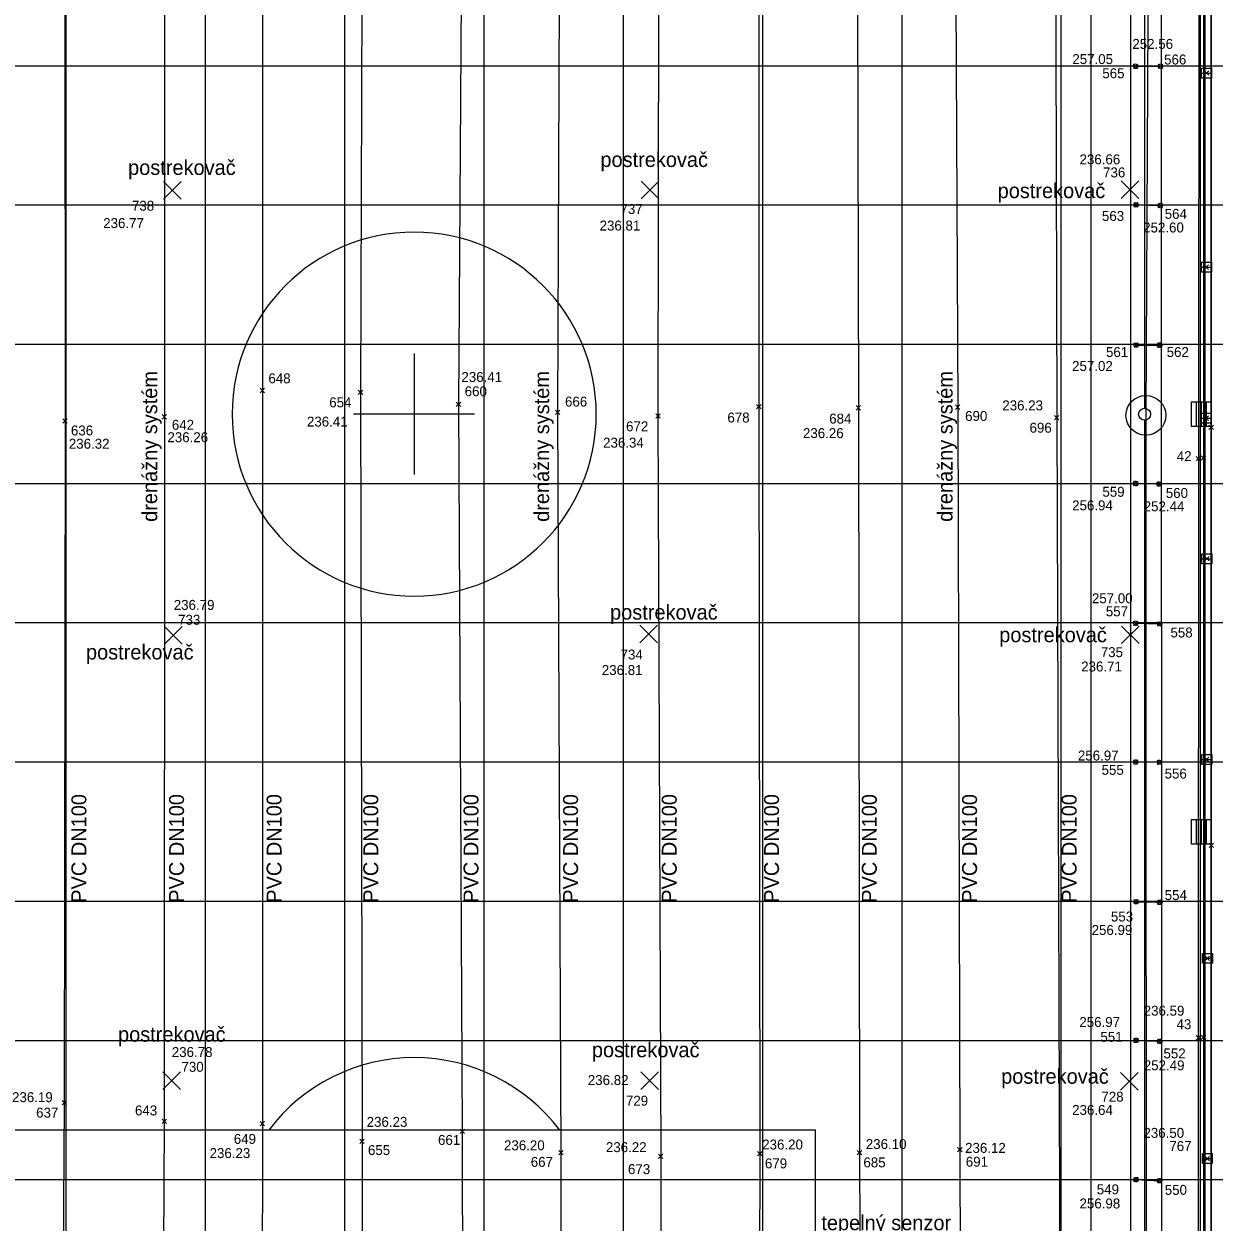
# Model space of a CAD drawing. Extents: x -264205 to -263659, y -1242401 to -1242060.
# Drawn here: x -263871.6 to -263811.8, y -1242205 to -1242144.8 of the extents above; entities that cross this region are included whole.
import ezdxf

# ---------------------------------------------------------------- set-up
doc = ezdxf.new("R2010")
doc.units = 0
for name, color, linetype in [('BOD_CISLO', 7, 'Continuous'), ('BOD_SYMBOL', 7, 'Continuous'), ('BOD_VYSKA', 7, 'Continuous'), ('KFA_SO_10-1_DRENAZNY_SYSTEM_IHRISKA', 7, 'Continuous'), ('KFA_SO_10-1_LIZATKA_POMOCNE', 7, 'Continuous'), ('KFA_SO_10-1_OBRUBNIKY_IHRISKO', 7, 'Continuous'), ('KFA_SO_10-1_POSTREKOVACE', 7, 'Continuous'), ('KFA_SO_10-1_STRECHY', 7, 'Continuous'), ('KFA_SO_10-1_TRIBUNA_C_OBVOD', 7, 'Continuous'), ('KFA_SO_10-1_VPUST_STADION_POKLOP', 7, 'Continuous'), ('KFA_SO_40-2-II_DAZDOVA_KANALIZACIA', 7, 'Continuous'), ('OSI_STAVBY_KFA', 7, 'Continuous'), ('POPIS', 7, 'Continuous'), ('SITUACIA_DSP_2D', 7, 'Continuous')]:
    doc.layers.add(name, color=color, linetype=linetype)

msp = doc.modelspace()

# ---------------------------------------------------------------- linework, layer by layer
at = {"layer": 'BOD_SYMBOL'}
for p, q in [((-263815.819, -1242147.002), (-263815.598, -1242146.781)), ((-263815.598, -1242147.002), (-263815.819, -1242146.781)), ((-263814.573, -1242147.002), (-263814.352, -1242146.782)), ((-263814.352, -1242147.002), (-263814.573, -1242146.782)), ((-263812.263, -1242147.35), (-263812.041, -1242147.13)), ((-263812.041, -1242147.35), (-263812.263, -1242147.13)), ((-263864.232, -1242153.24), (-263864.011, -1242153.019)), ((-263864.011, -1242153.24), (-263864.232, -1242153.019)), ((-263840.223, -1242153.231), (-263840.002, -1242153.009)), ((-263840.002, -1242153.231), (-263840.223, -1242153.009)), ((-263816.111, -1242153.208), (-263815.889, -1242152.987)), ((-263815.889, -1242153.208), (-263816.111, -1242152.987)), ((-263815.802, -1242153.971), (-263815.581, -1242153.749)), ((-263815.581, -1242153.971), (-263815.802, -1242153.749)), ((-263814.588, -1242154.007), (-263814.367, -1242153.785)), ((-263814.367, -1242154.007), (-263814.588, -1242153.785)), ((-263812.268, -1242157.105), (-263812.046, -1242156.883)), ((-263812.046, -1242157.105), (-263812.268, -1242156.883)), ((-263815.8, -1242161.024), (-263815.579, -1242160.802)), ((-263815.579, -1242161.024), (-263815.8, -1242160.802)), ((-263814.617, -1242161.025), (-263814.396, -1242160.805)), ((-263814.396, -1242161.025), (-263814.617, -1242160.805)), ((-263859.705, -1242163.305), (-263859.484, -1242163.083)), ((-263859.484, -1242163.305), (-263859.705, -1242163.083)), ((-263854.777, -1242163.391), (-263854.556, -1242163.171)), ((-263854.556, -1242163.391), (-263854.777, -1242163.171)), ((-263849.851, -1242163.995), (-263849.63, -1242163.774)), ((-263849.63, -1242163.995), (-263849.851, -1242163.774)), ((-263844.872, -1242164.406), (-263844.65, -1242164.184)), ((-263844.65, -1242164.406), (-263844.872, -1242164.184)), ((-263834.758, -1242164.12), (-263834.537, -1242163.9)), ((-263834.537, -1242164.12), (-263834.758, -1242163.9)), ((-263829.758, -1242164.176), (-263829.536, -1242163.954)), ((-263829.536, -1242164.176), (-263829.758, -1242163.954)), ((-263824.766, -1242164.144), (-263824.545, -1242163.923)), ((-263824.545, -1242164.144), (-263824.766, -1242163.923)), ((-263869.623, -1242164.833), (-263869.402, -1242164.613)), ((-263869.402, -1242164.833), (-263869.623, -1242164.613)), ((-263864.633, -1242164.63), (-263864.411, -1242164.409)), ((-263864.411, -1242164.63), (-263864.633, -1242164.409)), ((-263839.828, -1242164.58), (-263839.606, -1242164.36)), ((-263839.606, -1242164.58), (-263839.828, -1242164.36)), ((-263819.788, -1242164.676), (-263819.567, -1242164.454)), ((-263819.567, -1242164.676), (-263819.788, -1242164.454)), ((-263812.279, -1242164.695), (-263812.057, -1242164.475)), ((-263812.057, -1242164.695), (-263812.279, -1242164.475)), ((-263812.028, -1242165.156), (-263811.807, -1242164.934)), ((-263811.807, -1242165.156), (-263812.028, -1242164.934)), ((-263812.671, -1242166.732), (-263812.45, -1242166.512)), ((-263812.45, -1242166.732), (-263812.671, -1242166.512)), ((-263812.414, -1242166.701), (-263812.193, -1242166.481)), ((-263812.193, -1242166.701), (-263812.414, -1242166.481)), ((-263815.823, -1242167.981), (-263815.602, -1242167.759)), ((-263815.602, -1242167.981), (-263815.823, -1242167.759)), ((-263814.652, -1242168.004), (-263814.431, -1242167.782)), ((-263814.431, -1242168.004), (-263814.652, -1242167.782)), ((-263812.246, -1242171.764), (-263812.024, -1242171.542)), ((-263812.024, -1242171.764), (-263812.246, -1242171.542)), ((-263815.816, -1242175.007), (-263815.595, -1242174.785)), ((-263815.595, -1242175.007), (-263815.816, -1242174.785)), ((-263814.616, -1242175.042), (-263814.394, -1242174.822)), ((-263814.394, -1242175.042), (-263814.616, -1242174.822)), ((-263864.179, -1242175.617), (-263863.958, -1242175.396)), ((-263863.958, -1242175.617), (-263864.179, -1242175.396)), ((-263840.291, -1242175.542), (-263840.07, -1242175.32)), ((-263840.07, -1242175.542), (-263840.291, -1242175.32)), ((-263816.084, -1242175.586), (-263815.863, -1242175.366)), ((-263815.863, -1242175.586), (-263816.084, -1242175.366)), ((-263815.817, -1242181.98), (-263815.595, -1242181.758)), ((-263815.595, -1242181.98), (-263815.817, -1242181.758)), ((-263814.629, -1242181.995), (-263814.408, -1242181.775)), ((-263814.408, -1242181.995), (-263814.629, -1242181.775)), ((-263812.247, -1242181.855), (-263812.026, -1242181.633)), ((-263812.026, -1242181.855), (-263812.247, -1242181.633)), ((-263812.025, -1242186.164), (-263811.804, -1242185.943)), ((-263811.804, -1242186.164), (-263812.025, -1242185.943)), ((-263815.799, -1242189.008), (-263815.578, -1242188.788)), ((-263815.578, -1242189.008), (-263815.799, -1242188.788)), ((-263814.607, -1242189.032), (-263814.386, -1242188.812)), ((-263814.386, -1242189.032), (-263814.607, -1242188.812)), ((-263812.217, -1242191.85), (-263811.996, -1242191.629)), ((-263811.996, -1242191.85), (-263812.217, -1242191.629)), ((-263812.672, -1242195.849), (-263812.451, -1242195.627)), ((-263812.451, -1242195.849), (-263812.672, -1242195.627)), ((-263812.411, -1242195.823), (-263812.19, -1242195.603)), ((-263812.19, -1242195.823), (-263812.411, -1242195.603)), ((-263815.802, -1242195.974), (-263815.58, -1242195.752)), ((-263815.58, -1242195.974), (-263815.802, -1242195.752)), ((-263814.612, -1242196.022), (-263814.391, -1242195.802)), ((-263814.391, -1242196.022), (-263814.612, -1242195.802)), ((-263864.266, -1242198.005), (-263864.045, -1242197.784)), ((-263864.045, -1242198.005), (-263864.266, -1242197.784)), ((-263840.246, -1242197.997), (-263840.024, -1242197.775)), ((-263840.024, -1242197.997), (-263840.246, -1242197.775)), ((-263816.144, -1242198.029), (-263815.924, -1242197.808)), ((-263815.924, -1242198.029), (-263816.144, -1242197.808)), ((-263869.663, -1242199.113), (-263869.442, -1242198.893)), ((-263869.442, -1242199.113), (-263869.663, -1242198.893)), ((-263864.638, -1242200.049), (-263864.416, -1242199.828)), ((-263864.416, -1242200.049), (-263864.638, -1242199.828)), ((-263859.704, -1242200.166), (-263859.483, -1242199.944)), ((-263859.483, -1242200.166), (-263859.704, -1242199.944)), ((-263849.664, -1242200.552), (-263849.443, -1242200.33)), ((-263849.443, -1242200.552), (-263849.664, -1242200.33)), ((-263854.698, -1242201.046), (-263854.476, -1242200.826)), ((-263854.476, -1242201.046), (-263854.698, -1242200.826)), ((-263844.707, -1242201.623), (-263844.486, -1242201.403)), ((-263844.486, -1242201.623), (-263844.707, -1242201.403)), ((-263839.691, -1242201.799), (-263839.47, -1242201.579)), ((-263839.47, -1242201.799), (-263839.691, -1242201.579)), ((-263834.707, -1242201.667), (-263834.486, -1242201.445)), ((-263834.486, -1242201.667), (-263834.707, -1242201.445)), ((-263829.699, -1242201.623), (-263829.478, -1242201.403)), ((-263829.478, -1242201.623), (-263829.699, -1242201.403)), ((-263824.66, -1242201.465), (-263824.438, -1242201.245)), ((-263824.438, -1242201.465), (-263824.66, -1242201.245)), ((-263812.22, -1242201.921), (-263811.998, -1242201.7)), ((-263811.998, -1242201.921), (-263812.22, -1242201.7)), ((-263815.802, -1242202.975), (-263815.581, -1242202.755)), ((-263815.581, -1242202.975), (-263815.802, -1242202.755)), ((-263814.622, -1242203.032), (-263814.4, -1242202.811)), ((-263814.4, -1242203.032), (-263814.622, -1242202.811))]:
    msp.add_line(p, q, dxfattribs=at)
at = {"layer": 'KFA_SO_10-1_DRENAZNY_SYSTEM_IHRISKA'}
for p, q in [((-263869.556, -1242111.232), (-263869.513, -1242164.723)), ((-263864.517, -1242111.831), (-263864.522, -1242164.519)), ((-263859.568, -1242112.454), (-263859.595, -1242163.194)), ((-263854.492, -1242112.7), (-263854.666, -1242163.281)), ((-263849.405, -1242112.937), (-263849.741, -1242163.884)), ((-263844.574, -1242112.927), (-263844.761, -1242164.295)), ((-263839.653, -1242112.911), (-263839.717, -1242164.47)), ((-263834.662, -1242113.858), (-263834.648, -1242164.01)), ((-263829.735, -1242114.023), (-263829.647, -1242164.065)), ((-263824.874, -1242113.88), (-263824.655, -1242164.033))]:
    msp.add_line(p, q, dxfattribs=at)
for points in [[(-263819.808, -1242114.324), (-263819.677, -1242164.565), (-263819.485, -1242218.367)], [(-263859.595, -1242163.194), (-263859.594, -1242200.055), (-263859.624, -1242218.088)], [(-263854.666, -1242163.281), (-263854.587, -1242200.936), (-263854.584, -1242216.781)], [(-263849.741, -1242163.884), (-263849.553, -1242200.441), (-263849.516, -1242217.262)], [(-263844.761, -1242164.295), (-263844.596, -1242201.513), (-263844.587, -1242217.331)], [(-263834.648, -1242164.01), (-263834.596, -1242201.556), (-263834.64, -1242218.417)], [(-263829.647, -1242164.065), (-263829.589, -1242201.513), (-263829.518, -1242218.027)], [(-263824.655, -1242164.033), (-263824.549, -1242201.355), (-263824.496, -1242218.682)], [(-263869.513, -1242164.723), (-263869.552, -1242199.003), (-263869.699, -1242219.776)], [(-263864.522, -1242164.519), (-263864.527, -1242199.938), (-263864.632, -1242219.068)], [(-263839.717, -1242164.47), (-263839.58, -1242201.689), (-263839.608, -1242217.689)]]:
    msp.add_lwpolyline(points, dxfattribs=at)
at = {"layer": 'KFA_SO_10-1_LIZATKA_POMOCNE'}
for p, q in [((-263815.709, -1242146.891), (-263814.463, -1242146.892)), ((-263815.692, -1242153.86), (-263814.477, -1242153.896)), ((-263815.689, -1242160.913), (-263814.507, -1242160.915)), ((-263815.713, -1242167.87), (-263814.541, -1242167.893)), ((-263815.705, -1242174.896), (-263814.505, -1242174.932)), ((-263815.706, -1242181.869), (-263814.519, -1242181.885)), ((-263815.688, -1242188.898), (-263814.497, -1242188.922)), ((-263815.691, -1242195.863), (-263814.502, -1242195.912)), ((-263815.692, -1242202.865), (-263814.511, -1242202.921))]:
    msp.add_line(p, q, dxfattribs=at)
for centre, major_axis, ratio in [((-263815.709, -1242146.891), (0.022, -0.111), 0.955047), ((-263814.463, -1242146.892), (-0.008, -0.115), 0.990623), ((-263815.692, -1242153.86), (0.0495, 0.0979), 0.976376), ((-263814.477, -1242153.896), (0.104, -0.043), 0.992511), ((-263815.689, -1242160.913), (0.031, -0.105), 0.950619), ((-263814.507, -1242160.915), (0.0934, -0.0705), 0.992164), ((-263815.713, -1242167.87), (0.053, 0.107), 0.970811), ((-263814.541, -1242167.893), (0.107, 0.029), 0.998784), ((-263815.705, -1242174.896), (0.028, 0.113), 0.977707), ((-263814.505, -1242174.932), (0.0777, -0.0759), 0.907938), ((-263815.706, -1242181.869), (0.0648, 0.0887), 0.97856), ((-263814.519, -1242181.885), (0.103, -0.016), 0.997627), ((-263815.688, -1242188.898), (-0.014, -0.11), 0.978866), ((-263814.497, -1242188.922), (0.0814, -0.0864), 0.990444), ((-263815.691, -1242195.863), (0.0926, 0.0706), 0.985437), ((-263814.502, -1242195.912), (0.109, 0.032), 0.999252), ((-263815.692, -1242202.865), (-0.013, -0.114), 0.974636), ((-263814.511, -1242202.921), (-0.037, -0.106), 0.999546)]:
    msp.add_ellipse(centre, major_axis=major_axis, ratio=ratio, dxfattribs=at)
at = {"layer": 'KFA_SO_10-1_OBRUBNIKY_IHRISKO'}
for points in [[(-263812.554, -1242108.944), (-263812.55, -1242123.834), (-263812.543, -1242140.463), (-263812.561, -1242166.622), (-263812.562, -1242195.738), (-263812.559, -1242219.298)], [(-263812.302, -1242108.944), (-263812.301, -1242123.86), (-263812.298, -1242140.481), (-263812.303, -1242166.591), (-263812.301, -1242195.713), (-263812.296, -1242220.436)]]:
    msp.add_lwpolyline(points, dxfattribs=at)
at = {"layer": 'KFA_SO_10-1_POSTREKOVACE'}
for p, q in [((-263864.564, -1242153.571), (-263863.68, -1242152.687)), ((-263863.68, -1242153.571), (-263864.564, -1242152.687)), ((-263840.554, -1242153.562), (-263839.67, -1242152.678)), ((-263839.67, -1242153.562), (-263840.554, -1242152.678)), ((-263816.442, -1242153.539), (-263815.558, -1242152.655)), ((-263815.558, -1242153.539), (-263816.442, -1242152.655)), ((-263864.51, -1242175.948), (-263863.626, -1242175.064)), ((-263863.626, -1242175.948), (-263864.51, -1242175.064)), ((-263840.623, -1242175.873), (-263839.739, -1242174.989)), ((-263839.739, -1242175.873), (-263840.623, -1242174.989)), ((-263816.416, -1242175.918), (-263815.532, -1242175.034)), ((-263815.532, -1242175.918), (-263816.416, -1242175.034)), ((-263864.597, -1242198.336), (-263863.713, -1242197.452)), ((-263863.713, -1242198.336), (-263864.597, -1242197.452)), ((-263840.577, -1242198.328), (-263839.693, -1242197.444)), ((-263839.693, -1242198.328), (-263840.577, -1242197.444)), ((-263816.476, -1242198.36), (-263815.592, -1242197.476)), ((-263815.592, -1242198.36), (-263816.476, -1242197.476))]:
    msp.add_line(p, q, dxfattribs=at)
at = {"layer": 'KFA_SO_10-1_STRECHY'}
msp.add_line((-263814.432, -1242109.405), (-263814.411, -1242219.389), dxfattribs=at)
at = {"layer": 'KFA_SO_10-1_TRIBUNA_C_OBVOD'}
msp.add_lwpolyline([(-263811.9, -1242108.121), (-263811.778, -1242108.42), (-263811.904, -1242108.455), (-263811.9, -1242110.523), (-263811.9, -1242110.524), (-263811.903, -1242123.046), (-263811.913, -1242144.045), (-263811.917, -1242165.045), (-263811.915, -1242186.053), (-263811.913, -1242207.043), (-263811.91, -1242218.257), (-263811.909, -1242218.258), (-263811.907, -1242220.315), (-263811.793, -1242220.368), (-263811.913, -1242220.663)], dxfattribs=at)
at = {"layer": 'KFA_SO_10-1_VPUST_STADION_POKLOP'}
for p, q in [((-263812.152, -1242147.24), (-263812.152, -1242147.24)), ((-263812.157, -1242156.994), (-263812.157, -1242156.994)), ((-263812.168, -1242164.585), (-263812.168, -1242164.585)), ((-263812.135, -1242171.653), (-263812.135, -1242171.653)), ((-263812.137, -1242181.744), (-263812.137, -1242181.744)), ((-263812.106, -1242191.739), (-263812.106, -1242191.739)), ((-263812.109, -1242201.81), (-263812.109, -1242201.81))]:
    msp.add_line(p, q, dxfattribs=at)
for points in [[(-263812.402, -1242147.24), (-263812.402, -1242146.99), (-263811.902, -1242146.99), (-263811.902, -1242147.49), (-263812.402, -1242147.49), (-263812.402, -1242147.24), (-263811.902, -1242147.24)], [(-263812.407, -1242156.994), (-263812.407, -1242156.744), (-263811.907, -1242156.744), (-263811.907, -1242157.244), (-263812.407, -1242157.244), (-263812.407, -1242156.994), (-263811.907, -1242156.994)], [(-263812.418, -1242164.585), (-263812.418, -1242164.335), (-263811.918, -1242164.335), (-263811.918, -1242164.835), (-263812.418, -1242164.835), (-263812.418, -1242164.585), (-263811.918, -1242164.585)], [(-263812.385, -1242171.653), (-263812.385, -1242171.403), (-263811.885, -1242171.403), (-263811.885, -1242171.903), (-263812.385, -1242171.903), (-263812.385, -1242171.653), (-263811.885, -1242171.653)], [(-263812.387, -1242181.744), (-263812.387, -1242181.494), (-263811.887, -1242181.494), (-263811.887, -1242181.994), (-263812.387, -1242181.994), (-263812.387, -1242181.744), (-263811.887, -1242181.744)], [(-263812.356, -1242191.739), (-263812.356, -1242191.489), (-263811.856, -1242191.489), (-263811.856, -1242191.989), (-263812.356, -1242191.989), (-263812.356, -1242191.739), (-263811.856, -1242191.739)], [(-263812.359, -1242201.81), (-263812.359, -1242201.56), (-263811.859, -1242201.56), (-263811.859, -1242202.06), (-263812.359, -1242202.06), (-263812.359, -1242201.81), (-263811.859, -1242201.81)]]:
    msp.add_lwpolyline(points, dxfattribs=at)
at = {"layer": 'KFA_SO_40-2-II_DAZDOVA_KANALIZACIA'}
msp.add_lwpolyline([(-263814.907, -1242107.856), (-263815.198, -1242164.443), (-263815.189, -1242220.791), (-263852.152, -1242220.736), (-263888.701, -1242220.786), (-263906.731, -1242239.259)], dxfattribs=at)
msp.add_circle((-263815.198, -1242164.443), 1, dxfattribs=at)
at = {"layer": 'OSI_STAVBY_KFA'}
for p, q in [((-263869.468, -1242083.237), (-263869.468, -1242246.707)), ((-263862.468, -1242083.237), (-263862.468, -1242246.707)), ((-263855.468, -1242083.237), (-263855.468, -1242246.707)), ((-263848.468, -1242083.237), (-263848.468, -1242246.707)), ((-263841.468, -1242083.237), (-263841.468, -1242246.707)), ((-263834.468, -1242083.237), (-263834.468, -1242246.707)), ((-263827.468, -1242083.237), (-263827.468, -1242246.707)), ((-263819.468, -1242083.237), (-263819.468, -1242246.707)), ((-263812.468, -1242083.237), (-263812.468, -1242246.707)), ((-263792.653, -1242146.882), (-263909.343, -1242146.882)), ((-263792.653, -1242153.882), (-263909.343, -1242153.882)), ((-263792.653, -1242160.882), (-263909.343, -1242160.882)), ((-263792.653, -1242167.882), (-263909.343, -1242167.882)), ((-263792.653, -1242174.882), (-263909.343, -1242174.882)), ((-263792.653, -1242181.882), (-263909.343, -1242181.882)), ((-263792.653, -1242188.882), (-263909.343, -1242188.882)), ((-263792.653, -1242195.882), (-263917.263, -1242195.882)), ((-263792.653, -1242202.882), (-263909.343, -1242202.882))]:
    msp.add_line(p, q, dxfattribs=at)
at = {"layer": 'SITUACIA_DSP_2D'}
for p, q in [((-263815.263, -1242108.177), (-263815.263, -1242164.087)), ((-263815.968, -1242108.434), (-263815.968, -1242220.33)), ((-263812.218, -1242220.206), (-263812.218, -1242108.558)), ((-263811.918, -1242108.434), (-263811.918, -1242220.33)), ((-263811.918, -1242220.33), (-263811.918, -1242108.434)), ((-263817.968, -1242111.882), (-263817.968, -1242216.882)), ((-263851.973, -1242161.342), (-263851.973, -1242167.422)), ((-263811.918, -1242163.782), (-263812.918, -1242163.782)), ((-263812.918, -1242163.782), (-263812.918, -1242164.982)), ((-263812.668, -1242163.782), (-263812.668, -1242164.982)), ((-263812.418, -1242163.782), (-263812.418, -1242164.982)), ((-263812.168, -1242163.782), (-263812.168, -1242164.982)), ((-263848.933, -1242164.382), (-263855.013, -1242164.382)), ((-263815.263, -1242164.687), (-263815.263, -1242220.396)), ((-263812.918, -1242164.982), (-263811.918, -1242164.982)), ((-263811.918, -1242184.782), (-263812.918, -1242184.782)), ((-263812.918, -1242184.782), (-263812.918, -1242185.982)), ((-263812.668, -1242184.782), (-263812.668, -1242185.982)), ((-263812.418, -1242184.782), (-263812.418, -1242185.982)), ((-263812.168, -1242184.782), (-263812.168, -1242185.982)), ((-263812.918, -1242185.982), (-263811.918, -1242185.982)), ((-263831.808, -1242200.382), (-263872.128, -1242200.382)), ((-263831.808, -1242216.882), (-263831.808, -1242200.382))]:
    msp.add_line(p, q, dxfattribs=at)
msp.add_circle((-263815.263, -1242164.387), 0.3, dxfattribs=at)
for centre, start, end in [((-263851.968, -1242164.382), 0, 180), ((-263851.968, -1242164.382), 180, 0), ((-263851.968, -1242205.882), 36.94821, 143.05179)]:
    msp.add_arc(centre, 9.15, start, end, dxfattribs=at)

# ---------------------------------------------------------------- texts
at = {"layer": 'BOD_CISLO'}
for s, p in [('566', (-263814.282, -1242146.805)), ('565', (-263817.386, -1242147.495)), ('736', (-263817.348, -1242152.482)), ('738', (-263866.151, -1242154.156)), ('737', (-263841.6, -1242154.316)), ('564', (-263814.251, -1242154.564)), ('563', (-263817.407, -1242154.669)), ('561', (-263817.202, -1242161.512)), ('562', (-263814.153, -1242161.51)), ('648', (-263859.293, -1242162.833)), ('660', (-263849.429, -1242163.484)), ('654', (-263856.236, -1242164.04)), ('666', (-263844.387, -1242164.004)), ('678', (-263836.227, -1242164.803)), ('690', (-263824.281, -1242164.725)), ('642', (-263864.146, -1242165.169)), ('672', (-263841.32, -1242165.246)), ('684', (-263831.111, -1242164.857)), ('696', (-263821.044, -1242165.316)), ('636', (-263869.217, -1242165.453)), ('42', (-263813.646, -1242166.745)), ('559', (-263817.382, -1242168.536)), ('560', (-263814.196, -1242168.595)), ('733', (-263863.83, -1242174.969)), ('557', (-263817.21, -1242174.547)), ('558', (-263813.962, -1242175.609)), ('734', (-263841.595, -1242176.717)), ('735', (-263817.462, -1242176.598)), ('555', (-263817.424, -1242182.514)), ('556', (-263814.256, -1242182.703)), ('554', (-263814.252, -1242188.812)), ('553', (-263816.954, -1242189.889)), ('43', (-263813.657, -1242195.302)), ('551', (-263817.483, -1242195.936)), ('552', (-263814.313, -1242196.771)), ('730', (-263863.662, -1242197.445)), ('729', (-263841.327, -1242199.147)), ('728', (-263817.432, -1242198.945)), ('637', (-263870.966, -1242199.747)), ('643', (-263865.999, -1242199.637)), ('649', (-263861.033, -1242201.069)), ('661', (-263850.77, -1242201.119)), ('767', (-263814.017, -1242201.426)), ('655', (-263854.291, -1242201.63)), ('667', (-263846.109, -1242202.224)), ('673', (-263841.224, -1242202.589)), ('679', (-263834.341, -1242202.299)), ('685', (-263829.392, -1242202.249)), ('691', (-263824.247, -1242202.216)), ('549', (-263817.665, -1242203.606)), ('550', (-263814.248, -1242203.63))]:
    msp.add_text(s, height=0.5, dxfattribs=at).set_placement(p)
at = {"layer": 'BOD_VYSKA'}
for s, p in [('252.56', (-263815.876, -1242146.02)), ('257.05', (-263818.893, -1242146.784)), ('236.66', (-263818.531, -1242151.823)), ('236.77', (-263867.595, -1242155.029)), ('236.81', (-263842.65, -1242155.152)), ('252.60', (-263815.334, -1242155.25)), ('257.02', (-263818.906, -1242162.213)), ('236.41', (-263849.594, -1242162.765)), ('236.23', (-263822.412, -1242164.193)), ('236.41', (-263857.356, -1242165.008)), ('236.26', (-263864.368, -1242165.793)), ('236.26', (-263832.43, -1242165.587)), ('236.32', (-263869.323, -1242166.121)), ('236.34', (-263842.474, -1242166.066)), ('256.94', (-263818.902, -1242169.219)), ('252.44', (-263815.307, -1242169.267)), ('236.79', (-263864.049, -1242174.223)), ('257.00', (-263817.909, -1242173.889)), ('236.71', (-263818.448, -1242177.319)), ('236.81', (-263842.538, -1242177.496)), ('256.97', (-263818.614, -1242181.795)), ('256.99', (-263817.924, -1242190.566)), ('236.59', (-263815.307, -1242194.624)), ('256.97', (-263818.541, -1242195.194)), ('236.78', (-263864.148, -1242196.701)), ('252.49', (-263815.302, -1242197.368)), ('236.82', (-263843.242, -1242198.108)), ('236.19', (-263872.177, -1242198.97)), ('236.64', (-263818.902, -1242199.612)), ('236.23', (-263854.356, -1242200.212)), ('236.50', (-263815.321, -1242200.765)), ('236.20', (-263847.454, -1242201.39)), ('236.22', (-263842.333, -1242201.483)), ('236.20', (-263834.478, -1242201.35)), ('236.10', (-263829.272, -1242201.328)), ('236.12', (-263824.283, -1242201.52)), ('236.23', (-263862.249, -1242201.782)), ('256.98', (-263818.532, -1242204.313))]:
    msp.add_text(s, height=0.5, dxfattribs=at).set_placement(p)
at = {"layer": 'KFA_SO_10-1_DRENAZNY_SYSTEM_IHRISKA'}
for p in [(-263868.443, -1242188.946), (-263863.535, -1242188.946), (-263858.633, -1242188.946), (-263853.775, -1242188.946), (-263848.738, -1242188.946), (-263843.735, -1242188.946), (-263838.775, -1242188.946), (-263833.635, -1242188.946), (-263828.721, -1242188.946), (-263823.684, -1242188.946), (-263818.679, -1242188.946)]:
    msp.add_text('PVC DN100', height=0.75, rotation=90, dxfattribs=at).set_placement(p)
at = {"layer": 'POPIS'}
for s, p in [('postrekovač', (-263866.345, -1242152.357)), ('postrekovač', (-263842.609, -1242151.958)), ('postrekovač', (-263822.646, -1242153.523)), ('postrekovač', (-263842.123, -1242174.712)), ('postrekovač', (-263822.567, -1242175.848)), ('postrekovač', (-263868.461, -1242176.716)), ('postrekovač', (-263866.85, -1242195.93)), ('postrekovač', (-263843.037, -1242196.712)), ('postrekovač', (-263822.47, -1242198.045)), ('tepelný senzor', (-263831.506, -1242205.407))]:
    msp.add_text(s, height=0.75, dxfattribs=at).set_placement(p)
for p in [(-263864.883, -1242169.798), (-263845.185, -1242169.798), (-263824.915, -1242169.798)]:
    msp.add_text('drenážny systém', height=0.75, rotation=90, dxfattribs=at).set_placement(p)

doc.saveas('drawing.dxf')
